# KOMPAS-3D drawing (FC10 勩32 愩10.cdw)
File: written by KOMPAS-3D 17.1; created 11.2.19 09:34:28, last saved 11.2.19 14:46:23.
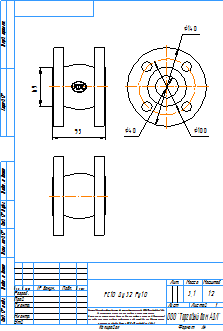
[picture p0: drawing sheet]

Sheet 1: A4, portrait

Title block, sheet 1: name: FC10 Ду32 Ру10; mass: 3,1; sheets: 1; sheet format: A4; stored path: \\adlc.lan\data\АДЛ_ПКД\3D-модели\ADL production\Гибкие вставки серии FC\FC10\KOMPAS 2D\FC10 Ду32 Ру10.cdw

Views: Вид 1
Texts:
  kka
  adl
  Рама для чертежей
  Лит-Масса-Масштаб
  Материал-Предприятие
  Масштаб
  Изм.
  Лист
  № докум.
  Подп.
  Дата
  Лит.
  Разраб.
  Пров.
  Т.контр.
  Листов
  Внимание! Данный продукт является объектом авторского права ООО «Торговый Дом АДЛ».
  Запрещается изменение, копирование, распространение
  (в том числе путем копирования на другие сайты и ресурсы в Интернете)
  или любое иное использование информации и объектов без предварительного
  согласия правообладателя (ООО «Торговый Дом АДЛ»).
  Н.контр.
  Утв.
  ООО "Торговый дом АДЛ"
  Изменение
  Номер документа
  Подпись
  Обозначение документа
  Наименование изделия
  Масса изделия по ГОСТ 2.109-73
  Порядковый номер листа
  Общее количество листов в документе
  Характер работы, выполненной лицом, подписавшим документ
  Наименование или индекс предприятия, выпускающего документ
  Инв. № подл.
  Подп. и дата
  Взам. инв. №
  Инв. № дубл.
  Инвентарный номер подлинника по ГОСТ 2.501-68
  Подпись принявшего подлинник в отдел технической документации
  Инвентарный номер подлинника, взамен которого выпущен данный подлинник
  Инвентарный номер дубликата по ГОСТ 2.502-68
  Подпись принявшего дубликат в отдел технической документации
  Справ. №
  Перв. примен.
  Обозначение документа, взамен или на основании которого выпущен данный документ
  Обозначение документа, в котором впервые записан данный документ
  Подпись лица, копировавшего чертеж
  Обозначение формата листа
  !Рама для чертежа
Dimensions and other numbers on the sheet: 95; 69; 40; 100; 140; 1:2; 1; 3,1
